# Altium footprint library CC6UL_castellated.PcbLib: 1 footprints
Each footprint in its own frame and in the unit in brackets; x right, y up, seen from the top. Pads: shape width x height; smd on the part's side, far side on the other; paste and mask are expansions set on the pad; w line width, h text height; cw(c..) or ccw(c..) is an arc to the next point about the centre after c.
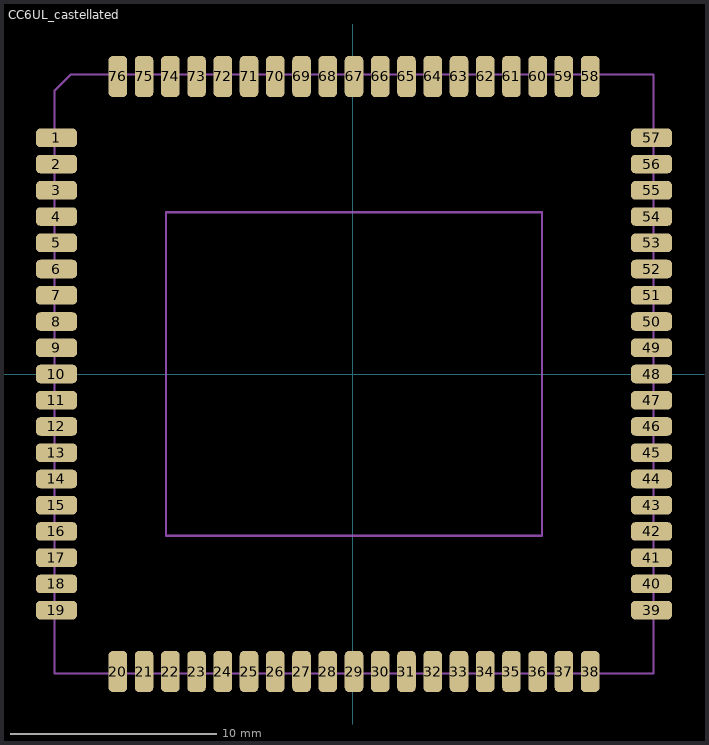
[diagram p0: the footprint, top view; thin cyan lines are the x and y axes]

## CC6UL_castellated [mm]
pads (76):
  rrect50% 2x0.9 smd: 1(-14.34,11.43) 2(-14.34,10.16) 3(-14.34,8.89) 4(-14.34,7.62) 5(-14.34,6.35) 6(-14.34,5.08) 7(-14.34,3.81) 8(-14.34,2.54) 9(-14.34,1.27) 10(-14.34,0) 11(-14.34,-1.27) 12(-14.34,-2.54) 13(-14.34,-3.81) 14(-14.34,-5.08) 15(-14.34,-6.35) 16(-14.34,-7.62) 17(-14.34,-8.89) 18(-14.34,-10.16) 19(-14.34,-11.43) 39(14.46,-11.43) 40(14.46,-10.16) 41(14.46,-8.89) 42(14.46,-7.62) 43(14.46,-6.35) 44(14.46,-5.08) 45(14.46,-3.81) 46(14.46,-2.54) 47(14.46,-1.27) 48(14.46,0) 49(14.46,1.27) 50(14.46,2.54) 51(14.46,3.81) 52(14.46,5.08) 53(14.46,6.35) 54(14.46,7.62) 55(14.46,8.89) 56(14.46,10.16) 57(14.46,11.43)
  rrect50% 0.9x2 smd: 20(-11.37,-14.4) 21(-10.1,-14.4) 22(-8.83,-14.4) 23(-7.56,-14.4) 24(-6.29,-14.4) 25(-5.02,-14.4) 26(-3.75,-14.4) 27(-2.48,-14.4) 28(-1.21,-14.4) 29(0.06,-14.4) 30(1.33,-14.4) 31(2.6,-14.4) 32(3.87,-14.4) 33(5.14,-14.4) 34(6.41,-14.4) 35(7.68,-14.4) 36(8.95,-14.4) 37(10.22,-14.4) 38(11.49,-14.4) 58(11.49,14.4) 59(10.22,14.4) 60(8.95,14.4) 61(7.68,14.4) 62(6.41,14.4) 63(5.14,14.4) 64(3.87,14.4) 65(2.6,14.4) 66(1.33,14.4) 67(0.06,14.4) 68(-1.21,14.4) 69(-2.48,14.4) 70(-3.75,14.4) 71(-5.02,14.4) 72(-6.29,14.4) 73(-7.56,14.4) 74(-8.83,14.4) 75(-10.1,14.4) 76(-11.37,14.4)
Mechanical 1:
  lines w0.102: -9.04,-7.83 9.16,-7.83 9.16,7.83 -9.04,7.83 -9.04,-7.82
Mechanical 3:
  lines w0.102: -14.44,-14.5 14.56,-14.5 14.56,14.5 -13.64,14.5 -14.44,13.7 -14.44,-14.5
  text ".Designator" at -3.87,-0.25 h1.02
3D body "55001875_pcba_ccimx6ul_asm_04-27.stp": height 4.35, standoff 0, extent -14.44,-14.5 14.56,17.356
